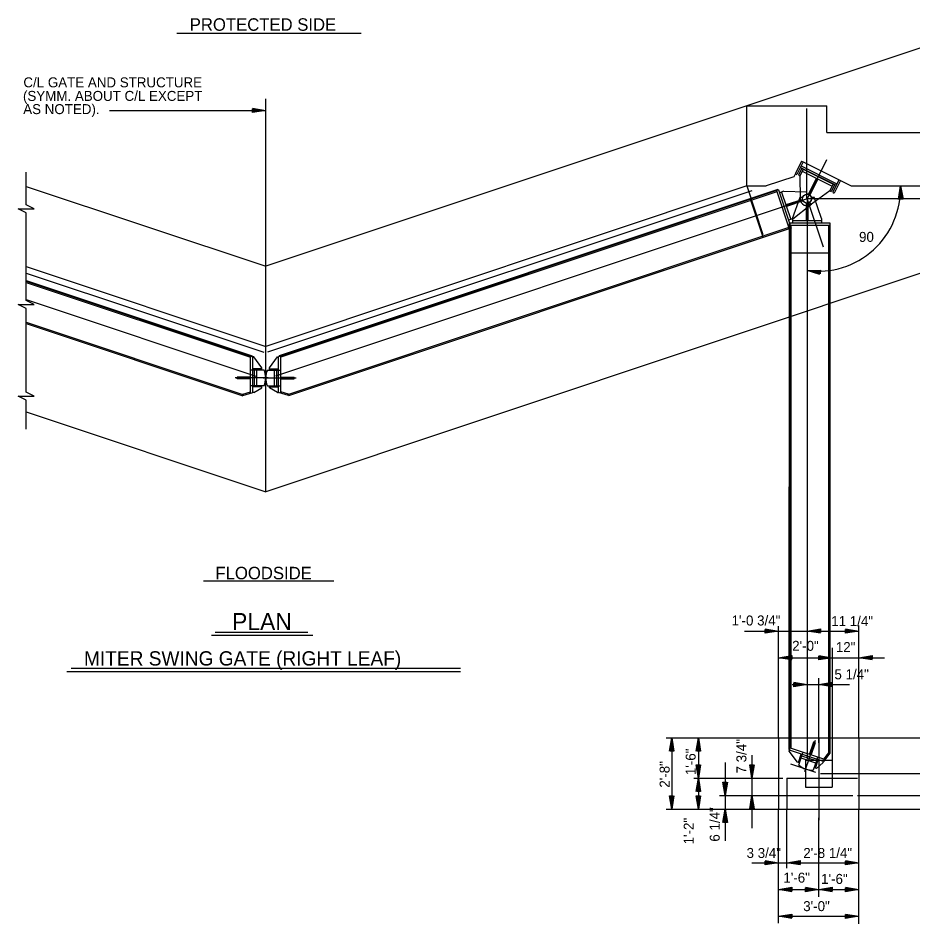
# Model space of a CAD drawing. Extents: x -48 to 108, y -5 to 100.
# Drawn here: x -48.32 to -14.84, y -5.19 to 28.69 of the extents above; entities that cross this region are included whole.
import ezdxf

# ---------------------------------------------------------------- set-up
doc = ezdxf.new("R2010")
doc.units = 0
for name, color, linetype in [('Level 13', 7, 'Continuous'), ('Level 2', 7, 'Continuous'), ('Level 25', 7, 'Continuous'), ('Level 50', 7, 'Continuous')]:
    doc.layers.add(name, color=color, linetype=linetype)

msp = doc.modelspace()

# ---------------------------------------------------------------- linework, layer by layer
at = {"layer": 'Level 13'}
for points in [[(-48.02, 21.399), (-48.32, 21.548), (-47.72, 21.548), (-48.02, 21.698)], [(-48.02, 21.399), (-48.32, 21.548), (-47.72, 21.548), (-48.02, 21.698)], [(-48.02, 17.832), (-48.32, 17.981), (-47.72, 17.981), (-48.02, 18.131)], [(-48.02, 14.393), (-48.32, 14.542), (-47.72, 14.542), (-48.02, 14.692)]]:
    msp.add_lwpolyline(points, dxfattribs=at)
at = {"layer": 'Level 25'}
for p, q in [((-42.387, 28.118), (-35.489, 28.118)), ((-13.837, 27.814), (-39.056, 19.408)), ((-39.056, 10.975), (-39.056, 25.667)), ((-21.056, 22.408), (-21.056, 25.408)), ((-21.056, 25.408), (-18.056, 25.408)), ((-18.056, 24.408), (-18.056, 25.408)), ((-44.896, 25.236), (-39.056, 25.236)), ((-18.806, 21.928), (-18.806, 25.303)), ((-18.056, 24.408), (-12.701, 24.408)), ((-18.074, 23.381), (-18.8, 21.93)), ((-19.005, 23.337), (-19.238, 22.871)), ((-18.949, 23.309), (-19.182, 22.843)), ((-18.995, 23.076), (-19.126, 22.815)), ((-18.939, 23.048), (-19.07, 22.787)), ((-19.051, 23.104), (-17.71, 22.433)), ((-19.023, 23.16), (-17.682, 22.489)), ((-19.005, 23.337), (-18.949, 23.309)), ((-19, 23.067), (-17.77, 22.452)), ((-18.949, 23.309), (-17.146, 22.408)), ((-48.02, 21.698), (-48.02, 22.927)), ((-19.297, 22.752), (-20.331, 22.408)), ((-19.238, 22.871), (-19.297, 22.752)), ((-19.238, 22.871), (-19.182, 22.843)), ((-19.126, 22.815), (-19.07, 22.787)), ((-19.07, 22.787), (-19.06, 21.931)), ((-18.981, 22.964), (-17.863, 22.405)), ((-18.45, 22.699), (-18.754, 22.09)), ((-48.02, 22.395), (-39.056, 19.408)), ((-21.056, 22.408), (-39.056, 16.408)), ((-21.056, 22.408), (-20.331, 22.408)), ((-21.056, 22.408), (-20.451, 20.592)), ((-18.394, 22.671), (-18.698, 22.062)), ((-17.821, 22.489), (-17.952, 22.228)), ((-17.765, 22.461), (-17.896, 22.2)), ((-17.607, 22.638), (-17.84, 22.172)), ((-17.551, 22.61), (-17.784, 22.144)), ((-17.607, 22.638), (-17.551, 22.61)), ((-17.146, 22.408), (-12.701, 22.408)), ((-20.87, 22.228), (-38.984, 16.19)), ((-19.867, 22.26), (-38.577, 16.023)), ((-19.895, 22.278), (-38.556, 16.058)), ((-19.931, 22.189), (-38.494, 16.002)), ((-19.946, 22.234), (-19.472, 20.811)), ((-19.895, 22.278), (-19.887, 22.253)), ((-19.867, 22.26), (-19.393, 20.837)), ((-19.674, 22.209), (-19.832, 22.157)), ((-19.753, 22.183), (-19.411, 21.155)), ((-19.674, 22.209), (-18.834, 22.193)), ((-18.834, 22.193), (-18.802, 22.097)), ((-17.952, 22.228), (-18.638, 21.726)), ((-17.952, 22.228), (-17.896, 22.2)), ((-17.84, 22.172), (-17.784, 22.144)), ((-18.8, 21.93), (-38.687, 15.301)), ((-20.931, 21.927), (-20.456, 20.504)), ((-18.965, 21.908), (-19.592, 21.699)), ((-18.945, 21.848), (-19.572, 21.639)), ((-19.341, 21.195), (-19.06, 21.987)), ((-19.332, 21.182), (-18.67, 21.699)), ((-19.06, 21.987), (-18.959, 21.987)), ((-18.831, 21.773), (-18.831, 21.112)), ((-18.82, 21.937), (-16.907, 21.936)), ((-18.806, 21.949), (-18.201, 20.134)), ((-18.8, 21.93), (-18.802, 0.973)), ((-18.768, 21.773), (-18.768, 21.112)), ((-18.702, 21.795), (-18.67, 21.699)), ((-18.641, 21.987), (-18.539, 21.987)), ((-18.258, 21.195), (-18.539, 21.987)), ((-16.907, 21.936), (-11.283, 21.936)), ((-48.02, 18.131), (-48.02, 21.399)), ((-19.332, 21.182), (-19.49, 21.129)), ((-19.476, 21.008), (-19.479, 1.337)), ((-19.476, 21.008), (-19.45, 21.008)), ((-19.45, 21.029), (-19.452, 1.307)), ((-19.45, 21.029), (-17.95, 21.028)), ((-19.341, 21.195), (-19.341, 21.029)), ((-19.341, 21.112), (-18.258, 21.112)), ((-18.258, 21.195), (-18.258, 21.028)), ((-17.95, 21.028), (-17.952, 1.198)), ((-19.393, 20.837), (-38.205, 14.566)), ((-19.486, 20.855), (-38.203, 14.616)), ((-19.45, 20.945), (-17.95, 20.945)), ((-19.404, 20.945), (-19.406, 1.379)), ((-17.997, 20.945), (-17.999, 1.216)), ((-12.701, 19.76), (-39.056, 10.975)), ((-19.471, 19.914), (-17.971, 19.914)), ((-48.02, 19.395), (-39.056, 16.408)), ((-48.02, 19.154), (-39.129, 16.19)), ((-48.02, 18.879), (-39.556, 16.058)), ((-48.02, 18.851), (-39.535, 16.023)), ((-48.02, 18.802), (-39.619, 16.002)), ((-48.02, 18.166), (-39.425, 15.301)), ((-48.02, 14.692), (-48.02, 17.832)), ((-48.02, 17.32), (-39.909, 14.616)), ((-48.02, 17.27), (-39.907, 14.566)), ((-39.841, 16.125), (-39.856, 16.081)), ((-39.619, 14.663), (-39.619, 16.051)), ((-39.556, 16.03), (-39.556, 16.058)), ((-39.535, 14.691), (-39.535, 16.023)), ((-39.494, 16.023), (-39.535, 16.023)), ((-39.202, 15.607), (-39.494, 16.023)), ((-38.91, 15.607), (-38.619, 16.023)), ((-38.619, 16.023), (-38.577, 16.023)), ((-38.577, 14.691), (-38.577, 16.023)), ((-38.556, 16.03), (-38.556, 16.058)), ((-38.494, 14.663), (-38.494, 16.051)), ((-38.271, 16.125), (-38.256, 16.081)), ((-39.202, 15.523), (-39.202, 15.607)), ((-38.91, 15.523), (-38.91, 15.607)), ((-39.619, 15.263), (-40.119, 15.263)), ((-40.119, 15.2), (-40.119, 15.263)), ((-39.535, 15.523), (-39.619, 15.523)), ((-39.202, 15.565), (-39.535, 15.565)), ((-39.119, 15.523), (-39.535, 15.523)), ((-39.473, 14.94), (-39.473, 15.523)), ((-39.389, 14.94), (-39.389, 15.523)), ((-38.994, 15.523), (-38.577, 15.523)), ((-38.91, 15.565), (-38.577, 15.565)), ((-38.723, 14.94), (-38.723, 15.523)), ((-38.639, 14.94), (-38.639, 15.523)), ((-38.577, 15.523), (-38.494, 15.523)), ((-38.494, 15.263), (-37.994, 15.263)), ((-37.994, 15.2), (-37.994, 15.263)), ((-38.959, 15.232), (-40.2, 15.232)), ((-38.959, 15.232), (-40.2, 15.232)), ((-39.619, 15.2), (-40.119, 15.2)), ((-39.535, 14.94), (-39.619, 14.94)), ((-39.118, 14.94), (-39.535, 14.941)), ((-39.119, 14.94), (-39.495, 14.94)), ((-39.202, 14.857), (-39.202, 14.94)), ((-39.202, 14.857), (-39.202, 14.94)), ((-39.153, 15.232), (-37.912, 15.232)), ((-39.153, 15.232), (-37.912, 15.232)), ((-38.994, 14.94), (-38.577, 14.941)), ((-38.994, 14.94), (-38.616, 14.94)), ((-38.91, 14.857), (-38.91, 14.94)), ((-38.91, 14.857), (-38.91, 14.94)), ((-38.577, 14.94), (-38.494, 14.94)), ((-38.494, 15.2), (-37.994, 15.2)), ((-39.907, 14.617), (-39.619, 14.712)), ((-39.907, 14.567), (-39.535, 14.691)), ((-39.907, 14.567), (-39.907, 14.617)), ((-39.202, 14.898), (-39.535, 14.899)), ((-39.202, 14.898), (-39.535, 14.898)), ((-39.494, 14.691), (-39.535, 14.691)), ((-39.494, 14.691), (-39.202, 14.857)), ((-38.91, 14.898), (-38.577, 14.899)), ((-38.91, 14.898), (-38.577, 14.898)), ((-38.619, 14.691), (-38.91, 14.857)), ((-38.619, 14.691), (-38.577, 14.691)), ((-38.205, 14.567), (-38.577, 14.691)), ((-38.205, 14.617), (-38.493, 14.712)), ((-38.205, 14.567), (-38.205, 14.617)), ((-48.02, 13.31), (-48.02, 14.393)), ((-48.02, 13.963), (-39.056, 10.975)), ((-41.385, 7.643), (-36.505, 7.643)), ((-21.136, 5.765), (-19.864, 5.765)), ((-19.864, 1.765), (-19.864, 5.945)), ((-19.864, 5.765), (-18.801, 5.765)), ((-18.801, 5.765), (-16.864, 5.765)), ((-16.864, 1.765), (-16.864, 5.969)), ((-41.089, 5.615), (-37.289, 5.615)), ((-40.946, 5.719), (-37.477, 5.719)), ((-17.864, 5.14), (-17.864, 1.765)), ((-19.864, 4.765), (-17.864, 4.765)), ((-17.864, 4.765), (-16.864, 4.765)), ((-16.864, 4.765), (-15.899, 4.764)), ((-46.495, 4.257), (-31.764, 4.257)), ((-46.334, 4.379), (-31.773, 4.379)), ((-19.358, 3.765), (-18.802, 3.765)), ((-18.802, 3.765), (-18.364, 3.765)), ((-18.364, 1.587), (-18.364, 4.003)), ((-18.364, 3.765), (-17.214, 3.765)), ((-24.078, 1.765), (-19.864, 1.765)), ((-23.864, 1.765), (-23.865, -0.902)), ((-22.864, 1.765), (-22.864, 0.265)), ((-19.864, 1.765), (-19.865, -0.902)), ((-19.864, 1.765), (-16.864, 1.765)), ((-18.364, 1.753), (-18.365, -1.303)), ((-17.864, 1.765), (-17.864, 0.265)), ((-16.864, 1.765), (-16.865, -0.902)), ((-16.864, 1.765), (-12.651, 1.765)), ((-19.452, 1.629), (-19.406, 1.629)), ((-18.136, 0.955), (-19.452, 1.394)), ((-18.884, 0.51), (-18.491, 1.687)), ((-18.884, 0.51), (-18.491, 1.687)), ((-18.705, 1.145), (-18.547, 1.619)), ((-18.645, 1.125), (-18.487, 1.6)), ((-18.487, 1.6), (-18.547, 1.619)), ((-20.864, 1.119), (-20.864, 0.265)), ((-19.452, 1.329), (-19.479, 1.337)), ((-19.466, 1.267), (-19.452, 1.307)), ((-19.163, 0.859), (-19.466, 1.267)), ((-18.188, 0.885), (-19.452, 1.307)), ((-19.123, 0.845), (-19.018, 1.162)), ((-19.11, 0.753), (-18.978, 1.148)), ((-18.445, 0.905), (-18.998, 1.089)), ((-18.978, 1.148), (-18.952, 1.227)), ((-18.425, 0.964), (-18.398, 1.043)), ((-17.954, 1.199), (-18.188, 0.885)), ((-18, 1.214), (-18.182, 0.971)), ((-17.954, 1.199), (-18, 1.214)), ((-21.864, 0.846), (-21.865, -0.381)), ((-18.469, 0.474), (-19.405, 0.786)), ((-19.084, 0.832), (-19.163, 0.859)), ((-18.471, 0.826), (-19.024, 1.01)), ((-18.864, 0.931), (-17.864, 0.931)), ((-18.864, 0.931), (-18.864, -0.069)), ((-18.557, 0.568), (-18.425, 0.964)), ((-18.557, 0.569), (-18.437, 0.927)), ((-18.491, 0.634), (-18.385, 0.951)), ((-18.491, 0.634), (-18.386, 0.951)), ((-18.201, 0.845), (-18.451, 0.621)), ((-18.201, 0.845), (-18.188, 0.885)), ((-17.864, 0.931), (-17.864, -0.069)), ((-18.451, 0.621), (-18.53, 0.648)), ((-18.451, 0.621), (-18.53, 0.648)), ((-18.304, 0.431), (-12.605, 0.431)), ((-23.036, 0.265), (-19.705, 0.265)), ((-22.864, 0.265), (-22.865, -0.902)), ((-20.864, 0.265), (-20.865, -0.381)), ((-19.552, 0.265), (-17.864, 0.265)), ((-19.552, 0.265), (-19.552, -0.902)), ((-18.822, 0.265), (-16.909, 0.265)), ((-18.864, -0.069), (-17.864, -0.069)), ((-22.079, -0.381), (-19.753, -0.381)), ((-21.865, -0.381), (-21.865, -0.902)), ((-20.865, -0.381), (-20.865, -1.605)), ((-19.753, -0.381), (-17.087, -0.381)), ((-16.909, -0.381), (-13.64, -0.381)), ((-24.078, -0.902), (-19.865, -0.902)), ((-21.865, -0.902), (-21.865, -2.079)), ((-19.865, -0.902), (-16.865, -0.902)), ((-19.865, -5.164), (-19.865, -0.902)), ((-19.552, -2.606), (-19.552, -0.902)), ((-16.865, -0.902), (-12.651, -0.902)), ((-16.865, -5.188), (-16.865, -0.902)), ((-18.365, -4.181), (-18.365, -1.22)), ((-19.552, -3.11), (-19.552, -2.21)), ((-20.868, -2.902), (-19.865, -2.902)), ((-20.868, -2.902), (-19.864, -2.902)), ((-19.865, -2.902), (-19.552, -2.902)), ((-19.552, -2.902), (-16.865, -2.902)), ((-19.865, -3.902), (-18.365, -3.902)), ((-18.365, -3.902), (-16.865, -3.902)), ((-19.865, -4.902), (-16.865, -4.902))]:
    msp.add_line(p, q, dxfattribs=at)
for centre in [(-18.8, 21.937), (-18.8, 21.93)]:
    msp.add_circle(centre, 0.167, dxfattribs=at)
for centre, radius, start, end in [((-18.389, 22.301), 3.083, 262.3412, 1.987), ((-18.8, 21.93), 0.26, 179.707, 308.3224), ((-39.768, 15.232), 0.712, 335.8105, 24.1895), ((-38.344, 15.232), 0.712, 155.8105, 204.1895), ((-18.628, 1.277), 0.712, 227.3695, 275.7486)]:
    msp.add_arc(centre, radius, start, end, dxfattribs=at)
at = {"layer": 'Level 50'}
for p, q in [((-39.195, 25.236), (-39.195, 25.236)), ((-39.056, 25.236), (-39.056, 25.236)), ((-15.308, 22.408), (-15.308, 22.408)), ((-15.304, 22.269), (-15.304, 22.269)), ((-18.8, 19.246), (-18.8, 19.246)), ((-18.663, 19.227), (-18.663, 19.227)), ((-20.003, 5.765), (-20.003, 5.765)), ((-19.864, 5.765), (-19.864, 5.765)), ((-18.801, 5.765), (-18.801, 5.765)), ((-18.663, 5.765), (-18.663, 5.765)), ((-17.003, 5.765), (-17.003, 5.765)), ((-16.864, 5.765), (-16.864, 5.765)), ((-19.864, 4.765), (-19.864, 4.765)), ((-19.726, 4.765), (-19.726, 4.765)), ((-18.003, 4.765), (-18.003, 4.765)), ((-17.864, 4.765), (-17.864, 4.765)), ((-16.864, 4.765), (-16.864, 4.765)), ((-16.726, 4.765), (-16.726, 4.765)), ((-18.94, 3.765), (-18.94, 3.765)), ((-18.802, 3.765), (-18.802, 3.765)), ((-18.364, 3.765), (-18.364, 3.765)), ((-18.225, 3.765), (-18.225, 3.765)), ((-23.864, 1.765), (-23.864, 1.765)), ((-22.864, 1.765), (-22.864, 1.765)), ((-23.864, 1.626), (-23.864, 1.626)), ((-22.864, 1.626), (-22.864, 1.626)), ((-22.864, 0.403), (-22.864, 0.403)), ((-20.864, 0.403), (-20.864, 0.403)), ((-22.864, 0.265), (-22.864, 0.265)), ((-22.864, 0.265), (-22.864, 0.265)), ((-22.864, 0.126), (-22.864, 0.126)), ((-20.864, 0.265), (-20.864, 0.265)), ((-21.865, -0.242), (-21.865, -0.242)), ((-21.865, -0.381), (-21.865, -0.381)), ((-20.865, -0.381), (-20.865, -0.381)), ((-20.865, -0.52), (-20.865, -0.52)), ((-23.865, -0.763), (-23.865, -0.763)), ((-23.865, -0.902), (-23.865, -0.902)), ((-22.865, -0.763), (-22.865, -0.763)), ((-22.865, -0.902), (-22.865, -0.902)), ((-21.865, -0.902), (-21.865, -0.902)), ((-21.865, -1.04), (-21.865, -1.04)), ((-20.003, -2.902), (-20.003, -2.902)), ((-19.865, -2.902), (-19.865, -2.902)), ((-19.552, -2.902), (-19.552, -2.902)), ((-19.413, -2.902), (-19.413, -2.902)), ((-17.004, -2.902), (-17.004, -2.902)), ((-16.865, -2.902), (-16.865, -2.902)), ((-19.865, -3.902), (-19.865, -3.902)), ((-19.726, -3.902), (-19.726, -3.902)), ((-18.503, -3.902), (-18.503, -3.902)), ((-18.365, -3.902), (-18.365, -3.902)), ((-18.365, -3.902), (-18.365, -3.902)), ((-18.226, -3.902), (-18.226, -3.902)), ((-17.003, -3.902), (-17.003, -3.902)), ((-16.865, -3.902), (-16.865, -3.902)), ((-19.865, -4.902), (-19.865, -4.902)), ((-19.726, -4.902), (-19.726, -4.902)), ((-17.003, -4.902), (-17.003, -4.902)), ((-16.865, -4.902), (-16.865, -4.902))]:
    msp.add_line(p, q, dxfattribs=at)
for points in [[(-39.555, 25.319), (-39.056, 25.236), (-39.555, 25.153), (-39.555, 25.295), (-39.195, 25.236), (-39.533, 25.18), (-39.533, 25.271), (-39.328, 25.236), (-39.512, 25.207), (-39.512, 25.244), (-39.467, 25.236)], [(-15.374, 21.906), (-15.308, 22.408), (-15.209, 21.912), (-15.35, 21.907), (-15.304, 22.269), (-15.236, 21.932), (-15.327, 21.929), (-15.299, 22.136), (-15.263, 21.953), (-15.301, 21.952), (-15.294, 21.997)], [(-18.317, 19.097), (-18.8, 19.246), (-18.295, 19.261), (-18.314, 19.121), (-18.663, 19.227), (-18.319, 19.238), (-18.331, 19.148), (-18.53, 19.209), (-18.344, 19.214), (-18.349, 19.177), (-18.393, 19.191)], [(-20.363, 5.848), (-19.864, 5.765), (-20.363, 5.682), (-20.363, 5.824), (-20.003, 5.765), (-20.342, 5.709), (-20.342, 5.8), (-20.136, 5.765), (-20.32, 5.736), (-20.32, 5.773), (-20.275, 5.765)], [(-18.303, 5.682), (-18.801, 5.765), (-18.303, 5.847), (-18.303, 5.706), (-18.663, 5.765), (-18.324, 5.821), (-18.324, 5.73), (-18.529, 5.765), (-18.345, 5.794), (-18.345, 5.757), (-18.391, 5.765)], [(-17.363, 5.847), (-16.864, 5.765), (-17.363, 5.682), (-17.363, 5.823), (-17.003, 5.765), (-17.342, 5.709), (-17.342, 5.799), (-17.136, 5.765), (-17.32, 5.735), (-17.32, 5.773), (-17.275, 5.765)], [(-19.366, 4.682), (-19.864, 4.765), (-19.366, 4.847), (-19.366, 4.706), (-19.726, 4.765), (-19.387, 4.821), (-19.387, 4.73), (-19.592, 4.765), (-19.408, 4.794), (-19.408, 4.757), (-19.454, 4.765)], [(-18.363, 4.847), (-17.864, 4.765), (-18.363, 4.682), (-18.363, 4.823), (-18.003, 4.765), (-18.341, 4.709), (-18.341, 4.799), (-18.136, 4.765), (-18.32, 4.735), (-18.32, 4.773), (-18.275, 4.765)], [(-16.366, 4.682), (-16.864, 4.765), (-16.366, 4.847), (-16.366, 4.706), (-16.726, 4.765), (-16.387, 4.821), (-16.387, 4.73), (-16.592, 4.765), (-16.408, 4.794), (-16.408, 4.757), (-16.454, 4.765)], [(-19.3, 3.847), (-18.802, 3.765), (-19.3, 3.682), (-19.3, 3.823), (-18.94, 3.765), (-19.279, 3.709), (-19.279, 3.799), (-19.074, 3.765), (-19.258, 3.735), (-19.258, 3.773), (-19.212, 3.765)], [(-17.865, 3.682), (-18.364, 3.765), (-17.865, 3.847), (-17.865, 3.706), (-18.225, 3.765), (-17.887, 3.821), (-17.887, 3.73), (-18.092, 3.765), (-17.908, 3.794), (-17.908, 3.757), (-17.953, 3.765)], [(-23.947, 1.266), (-23.864, 1.765), (-23.782, 1.266), (-23.923, 1.266), (-23.864, 1.626), (-23.808, 1.288), (-23.899, 1.288), (-23.864, 1.493), (-23.835, 1.309), (-23.872, 1.309), (-23.864, 1.354)], [(-22.947, 1.266), (-22.864, 1.765), (-22.782, 1.266), (-22.923, 1.266), (-22.864, 1.626), (-22.808, 1.288), (-22.899, 1.288), (-22.864, 1.493), (-22.835, 1.309), (-22.872, 1.309), (-22.864, 1.354)], [(-22.782, 0.763), (-22.864, 0.265), (-22.947, 0.763), (-22.806, 0.763), (-22.864, 0.403), (-22.92, 0.742), (-22.83, 0.742), (-22.864, 0.537), (-22.894, 0.721), (-22.856, 0.721), (-22.864, 0.675)], [(-20.782, 0.763), (-20.864, 0.265), (-20.947, 0.763), (-20.806, 0.763), (-20.864, 0.403), (-20.92, 0.742), (-20.83, 0.742), (-20.864, 0.537), (-20.894, 0.721), (-20.856, 0.721), (-20.864, 0.675)], [(-22.947, -0.234), (-22.864, 0.265), (-22.782, -0.234), (-22.923, -0.234), (-22.864, 0.126), (-22.808, -0.213), (-22.899, -0.213), (-22.864, -0.007), (-22.835, -0.191), (-22.872, -0.191), (-22.864, -0.146)], [(-21.782, 0.118), (-21.865, -0.381), (-21.947, 0.118), (-21.806, 0.118), (-21.865, -0.242), (-21.92, 0.097), (-21.83, 0.097), (-21.864, -0.109), (-21.894, 0.075), (-21.856, 0.075), (-21.864, 0.03)], [(-23.782, -0.403), (-23.865, -0.902), (-23.947, -0.403), (-23.806, -0.403), (-23.865, -0.763), (-23.921, -0.424), (-23.83, -0.424), (-23.865, -0.63), (-23.894, -0.446), (-23.857, -0.446), (-23.865, -0.491)], [(-22.782, -0.403), (-22.865, -0.902), (-22.947, -0.403), (-22.806, -0.403), (-22.865, -0.763), (-22.921, -0.424), (-22.83, -0.424), (-22.865, -0.63), (-22.894, -0.446), (-22.857, -0.446), (-22.865, -0.491)], [(-20.947, -0.88), (-20.865, -0.381), (-20.782, -0.88), (-20.923, -0.88), (-20.865, -0.52), (-20.809, -0.858), (-20.899, -0.858), (-20.865, -0.653), (-20.835, -0.837), (-20.873, -0.837), (-20.865, -0.792)], [(-21.947, -1.4), (-21.865, -0.902), (-21.782, -1.4), (-21.923, -1.4), (-21.865, -1.04), (-21.809, -1.379), (-21.899, -1.379), (-21.865, -1.174), (-21.835, -1.358), (-21.873, -1.358), (-21.865, -1.312)], [(-20.363, -2.819), (-19.865, -2.902), (-20.363, -2.984), (-20.363, -2.843), (-20.003, -2.902), (-20.342, -2.958), (-20.342, -2.867), (-20.137, -2.902), (-20.321, -2.931), (-20.321, -2.894), (-20.275, -2.902)], [(-19.053, -2.985), (-19.552, -2.902), (-19.053, -2.819), (-19.053, -2.961), (-19.413, -2.902), (-19.075, -2.846), (-19.075, -2.937), (-19.28, -2.902), (-19.096, -2.873), (-19.096, -2.91), (-19.141, -2.902)], [(-17.364, -2.819), (-16.865, -2.902), (-17.364, -2.985), (-17.364, -2.843), (-17.004, -2.902), (-17.342, -2.958), (-17.342, -2.867), (-17.137, -2.902), (-17.321, -2.931), (-17.321, -2.894), (-17.276, -2.902)], [(-19.366, -3.985), (-19.865, -3.902), (-19.366, -3.819), (-19.366, -3.961), (-19.726, -3.902), (-19.387, -3.846), (-19.387, -3.937), (-19.593, -3.902), (-19.409, -3.873), (-19.409, -3.91), (-19.454, -3.902)], [(-18.863, -3.819), (-18.365, -3.902), (-18.863, -3.985), (-18.863, -3.843), (-18.503, -3.902), (-18.842, -3.958), (-18.842, -3.867), (-18.637, -3.902), (-18.821, -3.931), (-18.821, -3.894), (-18.775, -3.902)], [(-17.866, -3.985), (-18.365, -3.902), (-17.866, -3.819), (-17.866, -3.961), (-18.226, -3.902), (-17.887, -3.846), (-17.887, -3.937), (-18.093, -3.902), (-17.909, -3.873), (-17.909, -3.91), (-17.954, -3.902)], [(-17.363, -3.819), (-16.865, -3.902), (-17.363, -3.985), (-17.363, -3.843), (-17.003, -3.902), (-17.342, -3.958), (-17.342, -3.867), (-17.137, -3.902), (-17.321, -3.931), (-17.321, -3.894), (-17.275, -3.902)], [(-19.366, -4.985), (-19.865, -4.902), (-19.366, -4.819), (-19.366, -4.961), (-19.726, -4.902), (-19.387, -4.846), (-19.387, -4.937), (-19.593, -4.902), (-19.409, -4.873), (-19.409, -4.91), (-19.454, -4.902)], [(-17.363, -4.819), (-16.865, -4.902), (-17.363, -4.985), (-17.363, -4.843), (-17.003, -4.902), (-17.342, -4.958), (-17.342, -4.867), (-17.137, -4.902), (-17.321, -4.931), (-17.321, -4.894), (-17.275, -4.902)]]:
    msp.add_lwpolyline(points, dxfattribs=at)

# ---------------------------------------------------------------- texts
at = {"layer": 'Level 2'}
for s, height, p in [('PLAN', 0.64, (-40.314, 5.797)), ('MITER SWING GATE (RIGHT LEAF)', 0.53432, (-45.854, 4.474))]:
    msp.add_text(s, height=height, dxfattribs=at).set_placement(p)
at = {"layer": 'Level 25'}
for s, height, p in [('PROTECTED SIDE', 0.46667, (-41.897, 28.213)), ('C/L GATE AND STRUCTURE', 0.37333, (-48.122, 26.097)), ('(SYMM. ABOUT C/L EXCEPT', 0.37333, (-48.137, 25.59)), ('AS NOTED).', 0.3733, (-48.128, 25.096)), ('90', 0.3733, (-16.856, 20.318)), ('FLOODSIDE', 0.4667, (-40.936, 7.699)), ('1\'-0 3/4"', 0.3733, (-21.625, 5.972)), ('11 1/4"', 0.3733, (-17.897, 5.948)), ('2\'-0"', 0.3733, (-19.358, 5.024)), ('12"', 0.3733, (-17.724, 4.977)), ('5 1/4"', 0.3733, (-17.776, 3.958)), ('3 3/4"', 0.3733, (-21.064, -2.722)), ('2\'-8 1/4"', 0.3733, (-18.942, -2.722)), ('1\'-6"', 0.3733, (-19.688, -3.645)), ('1\'-6"', 0.3733, (-18.275, -3.693)), ('3\'-0"', 0.3733, (-18.944, -4.711))]:
    msp.add_text(s, height=height, dxfattribs=at).set_placement(p)
for s, p in [('7 3/4"', (-21.07, 0.437)), ('1\'-6"', (-22.97, 0.376)), ('2\'-8"', (-23.944, -0.095)), ('6 1/4"', (-22.069, -2.112)), ('1\'-2"', (-23.043, -2.215))]:
    msp.add_text(s, height=0.3733, rotation=90, dxfattribs=at).set_placement(p)

doc.saveas('drawing.dxf')
